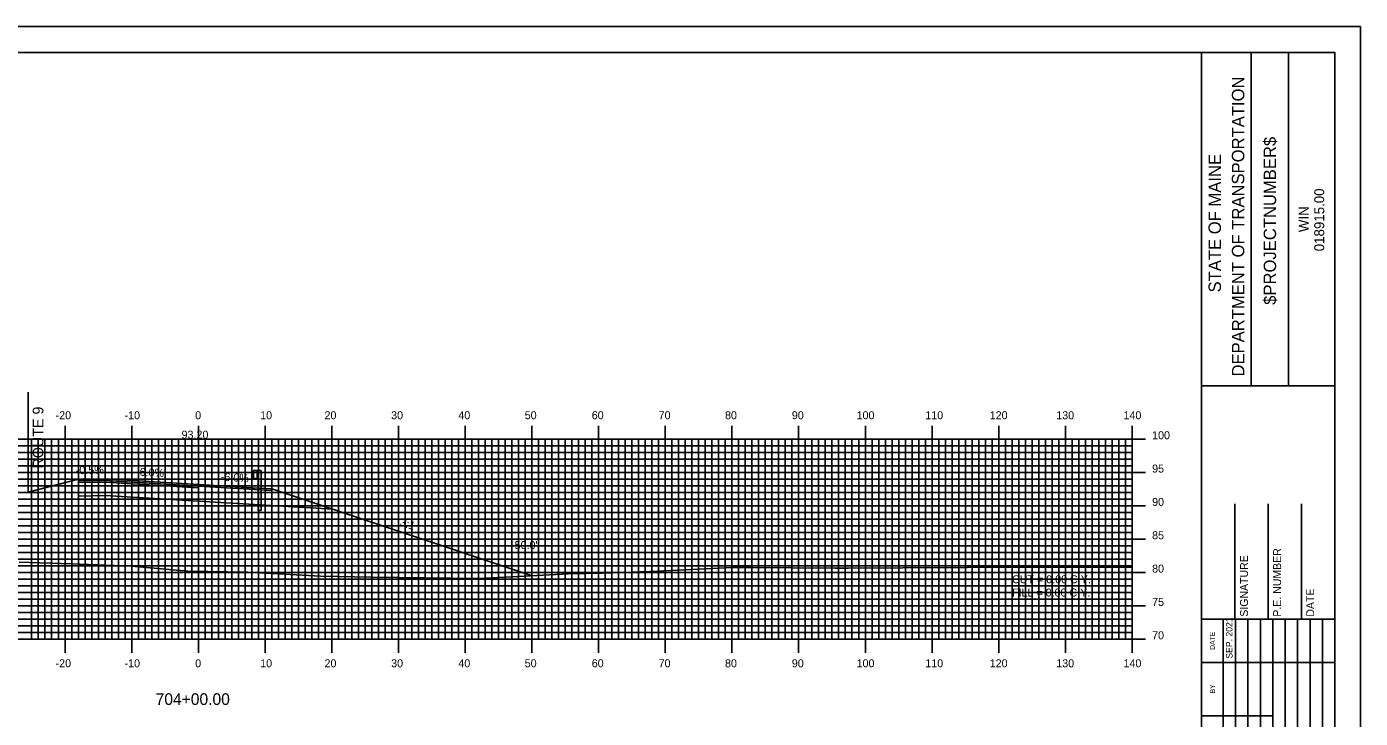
# Model space of a CAD drawing. Extents: x 853329 to 853673, y 364366 to 364586.
# Drawn here: x 853469.5 to 853669.4, y 364481.9 to 364585.7 of the extents above; entities that cross this region are included whole.
import ezdxf

# ---------------------------------------------------------------- set-up
doc = ezdxf.new("R2010")
doc.units = 0
for name, color, linetype in [('ANNOTATION', 7, 'Continuous'), ('BORDER', 7, 'Continuous'), ('D_Guardrail_Beam_Rt', 7, 'Continuous'), ('D_Roadway_Centerline_Text', 7, 'Continuous'), ('D_Roadway_Edge_Shoulder', 7, 'Continuous'), ('D_Roadway_Edge_TW', 7, 'Continuous'), ('D_Roadway_Pavement', 7, 'Continuous'), ('D_Roadway_SlopeLines', 7, 'Continuous'), ('D_Roadway_SubGrade', 7, 'Continuous'), ('D_Text_Standard', 7, 'Continuous'), ('H_V ANNOTATION', 7, 'Continuous'), ('MAJOR', 7, 'Continuous'), ('MINOR', 7, 'Continuous'), ('PLOT BOUNDARY', 7, 'Continuous'), ('S_Roadway_Centerline', 7, 'Continuous')]:
    doc.layers.add(name, color=color, linetype=linetype)

msp = doc.modelspace()

# ---------------------------------------------------------------- linework, layer by layer
at = {"layer": 'BORDER'}
for p, q in [((853645.6, 364371.79), (853645.6, 364581.79)), ((853653.06, 364531.78), (853653.06, 364581.78)), ((853658.65, 364531.78), (853658.65, 364581.78)), ((853645.61, 364531.78), (853665.6, 364531.78)), ((853650.6, 364496.79), (853650.6, 364514.09)), ((853655.6, 364496.79), (853655.6, 364514.09)), ((853660.6, 364496.79), (853660.6, 364514.09)), ((853645.6, 364496.79), (853665.6, 364496.79))]:
    msp.add_line(p, q, dxfattribs=at)
msp.add_lwpolyline([(853345.6, 364371.79), (853665.6, 364371.79), (853665.6, 364581.79), (853345.6, 364581.79)], close=True, dxfattribs=at)
for points in [[(853648.83, 364490.29), (853648.83, 364496.79)], [(853650.7, 364461.8), (853650.7, 364496.79)], [(853652.56, 364496.79), (853652.56, 364461.8)], [(853654.43, 364461.8), (853654.43, 364496.79)], [(853656.29, 364461.8), (853656.29, 364496.79)], [(853658.15, 364461.8), (853658.15, 364496.79)], [(853660.02, 364461.8), (853660.02, 364496.79)], [(853661.88, 364461.8), (853661.88, 364496.79)], [(853663.74, 364461.8), (853663.74, 364496.79)], [(853648.84, 364461.8), (853648.84, 364495.38)], [(853645.6, 364490.29), (853665.6, 364490.29)], [(853645.6, 364482.29), (853648.84, 364482.29)], [(853648.83, 364482.29), (853656.29, 364482.29)]]:
    msp.add_lwpolyline(points, dxfattribs=at)
at = {"layer": 'D_Guardrail_Beam_Rt'}
for p, q in [((853503.39, 364518.99), (853503.24, 364518.89)), ((853503.24, 364518.74), (853503.44, 364518.61)), ((853503.48, 364519.01), (853503.4, 364518.99)), ((853503.48, 364519.09), (853504.16, 364519.09)), ((853503.48, 364517.92), (853503.48, 364519.09)), ((853504, 364519.09), (853504, 364517.92)), ((853504.1, 364519.09), (853504.1, 364517.92)), ((853504.16, 364519.09), (853504.63, 364519.09)), ((853504.16, 364519.09), (853504.16, 364517.92)), ((853504.63, 364519.09), (853504.63, 364513.09)), ((853503.44, 364518.41), (853503.24, 364518.27)), ((853503.24, 364518.13), (853503.39, 364518.03)), ((853503.4, 364518.02), (853503.48, 364518.01)), ((853503.47, 364518.54), (853503.47, 364518.47)), ((853504.16, 364517.92), (853503.48, 364517.92)), ((853504.14, 364513.09), (853504.14, 364517.92)), ((853504.14, 364513.09), (853504.63, 364513.09))]:
    msp.add_line(p, q, dxfattribs=at)
for centre, major_axis, start_param, end_param in [((853503.29, 364518.81), (-0.0877, 0), 5.323254, 7.243116), ((853503.41, 364518.95), (-0.0417, 0), 4.907132, 5.323254), ((853503.29, 364518.2), (-0.0877, 0), 5.323254, 7.243116), ((853503.41, 364518.06), (-0.0417, 0), 0.959931, 1.376053), ((853503.39, 364518.54), (0.0789, 0), 0, 0.959931), ((853503.39, 364518.47), (0.0789, 0), 5.323254, 6.283185)]:
    msp.add_ellipse(centre, major_axis=major_axis, ratio=0.995501, start_param=start_param, end_param=end_param, dxfattribs=at)
at = {"layer": 'D_Roadway_Edge_Shoulder'}
for p, q in [((853477.2, 364517.37), (853477.2, 364517.81)), ((853481.2, 364517.58), (853477.2, 364517.56)), ((853481.2, 364517.33), (853477.2, 364517.31))]:
    msp.add_line(p, q, dxfattribs=at)
for points in [[(853481.2, 364517.83), (853477.2, 364517.81), (853469.7, 364515.87)], [(853481.2, 364515.33), (853477.2, 364515.25), (853477.2, 364517.37)]]:
    msp.add_lwpolyline(points, dxfattribs=at)
msp.add_lwpolyline([(853495.2, 364516.99), (853503.2, 364516.51), (853503.2, 364516.51), (853506.2, 364516.33), (853506.2, 364516.08), (853495.2, 364516.74)], close=True, dxfattribs=at)
at = {"layer": 'D_Roadway_Edge_TW'}
msp.add_lwpolyline([(853481.2, 364517.83), (853495.2, 364516.99), (853495.2, 364516.74), (853481.2, 364517.58)], close=True, dxfattribs=at)
at = {"layer": 'D_Roadway_Pavement'}
msp.add_lwpolyline([(853481.2, 364517.58), (853495.2, 364516.74), (853495.2, 364516.49), (853481.2, 364517.33)], close=True, dxfattribs=at)
msp.add_lwpolyline([(853495.2, 364516.74), (853495.2, 364516.49)], dxfattribs=at)
msp.add_lwpolyline([(853495.2, 364516.74), (853495.2, 364516.49)], dxfattribs=at)
msp.add_lwpolyline([(853495.2, 364516.74), (853495.2, 364516.49)], dxfattribs=at)
at = {"layer": 'D_Roadway_SlopeLines'}
msp.add_lwpolyline([(853506.2, 364516.33), (853545.23, 364503.32)], dxfattribs=at)
at = {"layer": 'D_Roadway_SubGrade'}
msp.add_line((853469.7, 364530.83), (853469.7, 364515.87), dxfattribs=at)
for points in [[(853481.2, 364517.33), (853495.2, 364516.49), (853495.2, 364514.49), (853481.2, 364515.33)], [(853495.2, 364516.49), (853495.2, 364516.74), (853506.2, 364516.08), (853506.2, 364516.33), (853515.35, 364513.28), (853495.2, 364514.49)]]:
    msp.add_lwpolyline(points, close=True, dxfattribs=at)
at = {"layer": 'MAJOR'}
for p, q in [((853475.2, 364525.79), (853475.2, 364523.79)), ((853485.2, 364525.79), (853485.2, 364523.79)), ((853495.2, 364525.79), (853495.2, 364523.79)), ((853505.2, 364525.79), (853505.2, 364523.79)), ((853515.2, 364525.79), (853515.2, 364523.79)), ((853525.2, 364525.79), (853525.2, 364523.79)), ((853535.2, 364525.79), (853535.2, 364523.79)), ((853545.2, 364525.79), (853545.2, 364523.79)), ((853555.2, 364525.79), (853555.2, 364523.79)), ((853565.2, 364525.79), (853565.2, 364523.79)), ((853575.2, 364525.79), (853575.2, 364523.79)), ((853585.2, 364525.79), (853585.2, 364523.79)), ((853595.2, 364525.79), (853595.2, 364523.79)), ((853605.2, 364525.79), (853605.2, 364523.79)), ((853615.2, 364525.79), (853615.2, 364523.79)), ((853625.2, 364525.79), (853625.2, 364523.79)), ((853635.2, 364525.79), (853635.2, 364523.79)), ((853355.2, 364523.79), (853635.2, 364523.79)), ((853355.2, 364523.79), (853635.2, 364523.79)), ((853475.2, 364493.79), (853475.2, 364523.79)), ((853485.2, 364493.79), (853485.2, 364523.79)), ((853495.2, 364493.79), (853495.2, 364523.79)), ((853505.2, 364493.79), (853505.2, 364523.79)), ((853515.2, 364493.79), (853515.2, 364523.79)), ((853525.2, 364493.79), (853525.2, 364523.79)), ((853535.2, 364493.79), (853535.2, 364523.79)), ((853545.2, 364493.79), (853545.2, 364523.79)), ((853555.2, 364493.79), (853555.2, 364523.79)), ((853565.2, 364493.79), (853565.2, 364523.79)), ((853575.2, 364493.79), (853575.2, 364523.79)), ((853585.2, 364493.79), (853585.2, 364523.79)), ((853595.2, 364493.79), (853595.2, 364523.79)), ((853605.2, 364493.79), (853605.2, 364523.79)), ((853615.2, 364493.79), (853615.2, 364523.79)), ((853625.2, 364493.79), (853625.2, 364523.79)), ((853637.21, 364523.79), (853633.2, 364523.79)), ((853635.2, 364493.79), (853635.2, 364523.79)), ((853635.2, 364493.79), (853635.2, 364523.79)), ((853355.2, 364518.79), (853635.2, 364518.79)), ((853637.21, 364518.79), (853633.2, 364518.79)), ((853355.2, 364513.79), (853635.2, 364513.79)), ((853637.21, 364513.79), (853633.2, 364513.79)), ((853355.2, 364508.79), (853635.2, 364508.79)), ((853637.21, 364508.79), (853633.2, 364508.79)), ((853355.2, 364503.79), (853635.2, 364503.79)), ((853637.21, 364503.79), (853633.2, 364503.79)), ((853355.2, 364498.79), (853635.2, 364498.79)), ((853637.21, 364498.79), (853633.2, 364498.79)), ((853355.2, 364493.79), (853635.2, 364493.79)), ((853355.2, 364493.79), (853635.2, 364493.79)), ((853475.2, 364491.78), (853475.2, 364493.79)), ((853485.2, 364491.78), (853485.2, 364493.79)), ((853495.2, 364491.78), (853495.2, 364493.79)), ((853505.2, 364491.78), (853505.2, 364493.79)), ((853515.2, 364491.78), (853515.2, 364493.79)), ((853525.2, 364491.78), (853525.2, 364493.79)), ((853535.2, 364491.78), (853535.2, 364493.79)), ((853545.2, 364491.78), (853545.2, 364493.79)), ((853555.2, 364491.78), (853555.2, 364493.79)), ((853565.2, 364491.78), (853565.2, 364493.79)), ((853575.2, 364491.78), (853575.2, 364493.79)), ((853585.2, 364491.78), (853585.2, 364493.79)), ((853595.2, 364491.78), (853595.2, 364493.79)), ((853605.2, 364491.78), (853605.2, 364493.79)), ((853615.2, 364491.78), (853615.2, 364493.79)), ((853625.2, 364491.78), (853625.2, 364493.79)), ((853637.21, 364493.79), (853633.2, 364493.79)), ((853635.2, 364491.78), (853635.2, 364493.79))]:
    msp.add_line(p, q, dxfattribs=at)
at = {"layer": 'MINOR'}
for p, q in [((853355.2, 364522.79), (853635.2, 364522.79)), ((853470.2, 364493.79), (853470.2, 364523.79)), ((853471.2, 364493.79), (853471.2, 364523.79)), ((853472.2, 364493.79), (853472.2, 364523.79)), ((853473.2, 364493.79), (853473.2, 364523.79)), ((853474.2, 364493.79), (853474.2, 364523.79)), ((853476.2, 364493.79), (853476.2, 364523.79)), ((853477.2, 364493.79), (853477.2, 364523.79)), ((853478.2, 364493.79), (853478.2, 364523.79)), ((853479.2, 364493.79), (853479.2, 364523.79)), ((853480.2, 364493.79), (853480.2, 364523.79)), ((853481.2, 364493.79), (853481.2, 364523.79)), ((853482.2, 364493.79), (853482.2, 364523.79)), ((853483.2, 364493.79), (853483.2, 364523.79)), ((853484.2, 364493.79), (853484.2, 364523.79)), ((853486.2, 364493.79), (853486.2, 364523.79)), ((853487.2, 364493.79), (853487.2, 364523.79)), ((853488.2, 364493.79), (853488.2, 364523.79)), ((853489.2, 364493.79), (853489.2, 364523.79)), ((853490.2, 364493.79), (853490.2, 364523.79)), ((853491.2, 364493.79), (853491.2, 364523.79)), ((853492.2, 364493.79), (853492.2, 364523.79)), ((853493.2, 364493.79), (853493.2, 364523.79)), ((853494.2, 364493.79), (853494.2, 364523.79)), ((853496.2, 364493.79), (853496.2, 364523.79)), ((853497.2, 364493.79), (853497.2, 364523.79)), ((853498.2, 364493.79), (853498.2, 364523.79)), ((853499.2, 364493.79), (853499.2, 364523.79)), ((853500.2, 364493.79), (853500.2, 364523.79)), ((853501.2, 364493.79), (853501.2, 364523.79)), ((853502.2, 364493.79), (853502.2, 364523.79)), ((853503.2, 364493.79), (853503.2, 364523.79)), ((853504.2, 364493.79), (853504.2, 364523.79)), ((853506.2, 364493.79), (853506.2, 364523.79)), ((853507.2, 364493.79), (853507.2, 364523.79)), ((853508.2, 364493.79), (853508.2, 364523.79)), ((853509.2, 364493.79), (853509.2, 364523.79)), ((853510.2, 364493.79), (853510.2, 364523.79)), ((853511.2, 364493.79), (853511.2, 364523.79)), ((853512.2, 364493.79), (853512.2, 364523.79)), ((853513.2, 364493.79), (853513.2, 364523.79)), ((853514.2, 364493.79), (853514.2, 364523.79)), ((853516.2, 364493.79), (853516.2, 364523.79)), ((853517.2, 364493.79), (853517.2, 364523.79)), ((853518.2, 364493.79), (853518.2, 364523.79)), ((853519.2, 364493.79), (853519.2, 364523.79)), ((853520.2, 364493.79), (853520.2, 364523.79)), ((853521.2, 364493.79), (853521.2, 364523.79)), ((853522.2, 364493.79), (853522.2, 364523.79)), ((853523.2, 364493.79), (853523.2, 364523.79)), ((853524.2, 364493.79), (853524.2, 364523.79)), ((853526.2, 364493.79), (853526.2, 364523.79)), ((853527.2, 364493.79), (853527.2, 364523.79)), ((853528.2, 364493.79), (853528.2, 364523.79)), ((853529.2, 364493.79), (853529.2, 364523.79)), ((853530.2, 364493.79), (853530.2, 364523.79)), ((853531.2, 364493.79), (853531.2, 364523.79)), ((853532.2, 364493.79), (853532.2, 364523.79)), ((853533.2, 364493.79), (853533.2, 364523.79)), ((853534.2, 364493.79), (853534.2, 364523.79)), ((853536.2, 364493.79), (853536.2, 364523.79)), ((853537.2, 364493.79), (853537.2, 364523.79)), ((853538.2, 364493.79), (853538.2, 364523.79)), ((853539.2, 364493.79), (853539.2, 364523.79)), ((853540.2, 364493.79), (853540.2, 364523.79)), ((853541.2, 364493.79), (853541.2, 364523.79)), ((853542.2, 364493.79), (853542.2, 364523.79)), ((853543.2, 364493.79), (853543.2, 364523.79)), ((853544.2, 364493.79), (853544.2, 364523.79)), ((853546.2, 364493.79), (853546.2, 364523.79)), ((853547.2, 364493.79), (853547.2, 364523.79)), ((853548.2, 364493.79), (853548.2, 364523.79)), ((853549.2, 364493.79), (853549.2, 364523.79)), ((853550.2, 364493.79), (853550.2, 364523.79)), ((853551.2, 364493.79), (853551.2, 364523.79)), ((853552.2, 364493.79), (853552.2, 364523.79)), ((853553.2, 364493.79), (853553.2, 364523.79)), ((853554.2, 364493.79), (853554.2, 364523.79)), ((853556.2, 364493.79), (853556.2, 364523.79)), ((853557.2, 364493.79), (853557.2, 364523.79)), ((853558.2, 364493.79), (853558.2, 364523.79)), ((853559.2, 364493.79), (853559.2, 364523.79)), ((853560.2, 364493.79), (853560.2, 364523.79)), ((853561.2, 364493.79), (853561.2, 364523.79)), ((853562.2, 364493.79), (853562.2, 364523.79)), ((853563.2, 364493.79), (853563.2, 364523.79)), ((853564.2, 364493.79), (853564.2, 364523.79)), ((853566.2, 364493.79), (853566.2, 364523.79)), ((853567.2, 364493.79), (853567.2, 364523.79)), ((853568.2, 364493.79), (853568.2, 364523.79)), ((853569.2, 364493.79), (853569.2, 364523.79)), ((853570.2, 364493.79), (853570.2, 364523.79)), ((853571.2, 364493.79), (853571.2, 364523.79)), ((853572.2, 364493.79), (853572.2, 364523.79)), ((853573.2, 364493.79), (853573.2, 364523.79)), ((853574.2, 364493.79), (853574.2, 364523.79)), ((853576.2, 364493.79), (853576.2, 364523.79)), ((853577.2, 364493.79), (853577.2, 364523.79)), ((853578.2, 364493.79), (853578.2, 364523.79)), ((853579.2, 364493.79), (853579.2, 364523.79)), ((853580.2, 364493.79), (853580.2, 364523.79)), ((853581.2, 364493.79), (853581.2, 364523.79)), ((853582.2, 364493.79), (853582.2, 364523.79)), ((853583.2, 364493.79), (853583.2, 364523.79)), ((853584.2, 364493.79), (853584.2, 364523.79)), ((853586.2, 364493.79), (853586.2, 364523.79)), ((853587.2, 364493.79), (853587.2, 364523.79)), ((853588.2, 364493.79), (853588.2, 364523.79)), ((853589.2, 364493.79), (853589.2, 364523.79)), ((853590.2, 364493.79), (853590.2, 364523.79)), ((853591.2, 364493.79), (853591.2, 364523.79)), ((853592.2, 364493.79), (853592.2, 364523.79)), ((853593.2, 364493.79), (853593.2, 364523.79)), ((853594.2, 364493.79), (853594.2, 364523.79)), ((853596.2, 364493.79), (853596.2, 364523.79)), ((853597.2, 364493.79), (853597.2, 364523.79)), ((853598.2, 364493.79), (853598.2, 364523.79)), ((853599.2, 364493.79), (853599.2, 364523.79)), ((853600.2, 364493.79), (853600.2, 364523.79)), ((853601.2, 364493.79), (853601.2, 364523.79)), ((853602.2, 364493.79), (853602.2, 364523.79)), ((853603.2, 364493.79), (853603.2, 364523.79)), ((853604.2, 364493.79), (853604.2, 364523.79)), ((853606.2, 364493.79), (853606.2, 364523.79)), ((853607.2, 364493.79), (853607.2, 364523.79)), ((853608.2, 364493.79), (853608.2, 364523.79)), ((853609.2, 364493.79), (853609.2, 364523.79)), ((853610.2, 364493.79), (853610.2, 364523.79)), ((853611.2, 364493.79), (853611.2, 364523.79)), ((853612.2, 364493.79), (853612.2, 364523.79)), ((853613.2, 364493.79), (853613.2, 364523.79)), ((853614.2, 364493.79), (853614.2, 364523.79)), ((853616.2, 364493.79), (853616.2, 364523.79)), ((853617.2, 364493.79), (853617.2, 364523.79)), ((853618.2, 364493.79), (853618.2, 364523.79)), ((853619.2, 364493.79), (853619.2, 364523.79)), ((853620.2, 364493.79), (853620.2, 364523.79)), ((853621.2, 364493.79), (853621.2, 364523.79)), ((853622.2, 364493.79), (853622.2, 364523.79)), ((853623.2, 364493.79), (853623.2, 364523.79)), ((853624.2, 364493.79), (853624.2, 364523.79)), ((853626.2, 364493.79), (853626.2, 364523.79)), ((853627.2, 364493.79), (853627.2, 364523.79)), ((853628.2, 364493.79), (853628.2, 364523.79)), ((853629.2, 364493.79), (853629.2, 364523.79)), ((853630.2, 364493.79), (853630.2, 364523.79)), ((853631.2, 364493.79), (853631.2, 364523.79)), ((853632.2, 364493.79), (853632.2, 364523.79)), ((853633.2, 364493.79), (853633.2, 364523.79)), ((853635.2, 364522.79), (853633.2, 364522.79)), ((853634.2, 364493.79), (853634.2, 364523.79)), ((853355.2, 364521.79), (853635.2, 364521.79)), ((853355.2, 364520.79), (853635.2, 364520.79)), ((853635.2, 364521.79), (853633.2, 364521.79)), ((853635.2, 364520.79), (853633.2, 364520.79)), ((853355.2, 364519.79), (853635.2, 364519.79)), ((853635.2, 364519.79), (853633.2, 364519.79)), ((853355.2, 364517.79), (853635.2, 364517.79)), ((853355.2, 364516.79), (853635.2, 364516.79)), ((853635.2, 364517.79), (853633.2, 364517.79)), ((853635.2, 364516.79), (853633.2, 364516.79)), ((853355.2, 364515.79), (853635.2, 364515.79)), ((853355.2, 364514.79), (853635.2, 364514.79)), ((853635.2, 364515.79), (853633.2, 364515.79)), ((853635.2, 364514.79), (853633.2, 364514.79)), ((853355.2, 364512.79), (853635.2, 364512.79)), ((853635.2, 364512.79), (853633.2, 364512.79)), ((853355.2, 364511.79), (853635.2, 364511.79)), ((853355.2, 364510.79), (853635.2, 364510.79)), ((853635.2, 364511.79), (853633.2, 364511.79)), ((853635.2, 364510.79), (853633.2, 364510.79)), ((853355.2, 364509.79), (853635.2, 364509.79)), ((853635.2, 364509.79), (853633.2, 364509.79)), ((853355.2, 364507.79), (853635.2, 364507.79)), ((853355.2, 364506.79), (853635.2, 364506.79)), ((853635.2, 364507.79), (853633.2, 364507.79)), ((853635.2, 364506.79), (853633.2, 364506.79)), ((853355.2, 364505.79), (853635.2, 364505.79)), ((853355.2, 364504.79), (853635.2, 364504.79)), ((853635.2, 364505.79), (853633.2, 364505.79)), ((853635.2, 364504.79), (853633.2, 364504.79)), ((853355.2, 364502.79), (853635.2, 364502.79)), ((853635.2, 364502.79), (853633.2, 364502.79)), ((853355.2, 364501.79), (853635.2, 364501.79)), ((853355.2, 364500.79), (853635.2, 364500.79)), ((853635.2, 364501.79), (853633.2, 364501.79)), ((853635.2, 364500.79), (853633.2, 364500.79)), ((853355.2, 364499.79), (853635.2, 364499.79)), ((853635.2, 364499.79), (853633.2, 364499.79)), ((853355.2, 364497.79), (853635.2, 364497.79)), ((853355.2, 364496.79), (853635.2, 364496.79)), ((853635.2, 364497.79), (853633.2, 364497.79)), ((853635.2, 364496.79), (853633.2, 364496.79)), ((853355.2, 364495.79), (853635.2, 364495.79)), ((853355.2, 364494.79), (853635.2, 364494.79)), ((853635.2, 364495.79), (853633.2, 364495.79)), ((853635.2, 364494.79), (853633.2, 364494.79))]:
    msp.add_line(p, q, dxfattribs=at)
at = {"layer": 'PLOT BOUNDARY'}
msp.add_lwpolyline([(853329.42, 364365.67), (853669.42, 364365.67), (853669.42, 364585.67), (853329.42, 364585.67)], close=True, dxfattribs=at)
at = {"layer": 'S_Roadway_Centerline'}
msp.add_lwpolyline([(853468.35, 364505.35), (853476.14, 364505.13), (853485.19, 364504.78), (853493.64, 364504.02), (853502.62, 364503.87), (853513.52, 364503.27), (853521.17, 364503.1), (853537.03, 364502.91), (853537.27, 364502.9), (853537.36, 364502.89), (853550.67, 364503.61), (853555.81, 364503.73), (853562.93, 364503.98), (853575.27, 364504.57), (853575.9, 364504.56), (853577.95, 364504.55), (853590.7, 364504.46), (853592.61, 364504.46), (853600.81, 364504.5), (853610.45, 364504.56), (853622.27, 364504.61), (853626.43, 364504.6), (853628.46, 364504.63), (853635.2, 364504.57)], dxfattribs=at)

# ---------------------------------------------------------------- texts
at = {"layer": 'ANNOTATION'}
for s, height, rotation, p in [('ROUTE 9', 1.6, 90, (853471.96, 364519.41)), ('-0.5%', 1.2, 1.1458, (853476.83, 364518.54)), ('6.0%', 1.2, 356.5664, (853486.36, 364518.32)), ('-6.0%', 1.2, 356.5664, (853498.54, 364517.59)), ('3:1', 1.2, 341.5651, (853525.32, 364510.86))]:
    msp.add_text(s, height=height, rotation=rotation, dxfattribs=at).set_placement(p)
at = {"layer": 'BORDER'}
for s, height, p in [('DEPARTMENT OF TRANSPORTATION', 1.8635, (853652.02, 364533.2)), ('$PROJECTNUMBER$', 1.8635, (853656.79, 364543.95)), ('STATE OF MAINE', 1.8635, (853648.52, 364545.81)), ('018915.00', 1.491, (853664, 364551.98)), ('WIN', 1.491, (853661.68, 364554.85)), ('P.E. NUMBER', 1.1811, (853657.53, 364497.18)), ('SIGNATURE', 1.181, (853652.57, 364497.18)), ('DATE', 1.181, (853662.49, 364497.18)), ('SEP. 2021', 0.969, (853650.25, 364490.88)), ('DATE', 0.743, (853647.61, 364492.2)), ('BY', 0.743, (853647.61, 364485.66))]:
    msp.add_text(s, height=height, rotation=90, dxfattribs=at).set_placement(p)
at = {"layer": 'D_Roadway_Centerline_Text'}
msp.add_text('93.20', height=1.2, dxfattribs=at).set_placement((853492.68, 364523.88))
at = {"layer": 'D_Text_Standard'}
for s, p in [("50.0'", (853542.62, 364507.32)), ('CUT = 0.00 C.Y.', (853617.2, 364502.19)), ('FILL = 0.00 C.Y.', (853617.2, 364500.2))]:
    msp.add_text(s, height=1.2, dxfattribs=at).set_placement(p)
at = {"layer": 'H_V ANNOTATION'}
for s, height, p in [('-20', 1.2, (853473.79, 364526.79)), ('-10', 1.2, (853484.13, 364526.79)), ('0', 1.2, (853494.72, 364526.79)), ('10', 1.2, (853504.46, 364526.79)), ('20', 1.2, (853514.11, 364526.79)), ('30', 1.2, (853524.1, 364526.79)), ('40', 1.2, (853534.18, 364526.79)), ('50', 1.2, (853544.13, 364526.79)), ('60', 1.2, (853554.18, 364526.79)), ('70', 1.2, (853564.21, 364526.79)), ('80', 1.2, (853574.16, 364526.79)), ('90', 1.2, (853584.18, 364526.79)), ('100', 1.2, (853593.89, 364526.79)), ('110', 1.2, (853604.19, 364526.79)), ('120', 1.2, (853613.85, 364526.79)), ('130', 1.2, (853623.83, 364526.79)), ('140', 1.2, (853633.91, 364526.79)), ('100', 1.2, (853638.2, 364523.79)), ('95', 1.2, (853638.2, 364518.79)), ('90', 1.2, (853638.2, 364513.79)), ('85', 1.2, (853638.2, 364508.79)), ('80', 1.2, (853638.2, 364503.79)), ('75', 1.2, (853638.2, 364498.79)), ('70', 1.2, (853638.2, 364493.79)), ('-20', 1.2, (853473.79, 364489.59)), ('-10', 1.2, (853484.13, 364489.59)), ('0', 1.2, (853494.72, 364489.59)), ('10', 1.2, (853504.46, 364489.59)), ('20', 1.2, (853514.11, 364489.59)), ('30', 1.2, (853524.1, 364489.59)), ('40', 1.2, (853534.18, 364489.59)), ('50', 1.2, (853544.13, 364489.59)), ('60', 1.2, (853554.18, 364489.59)), ('70', 1.2, (853564.21, 364489.59)), ('80', 1.2, (853574.16, 364489.59)), ('90', 1.2, (853584.18, 364489.59)), ('100', 1.2, (853593.89, 364489.59)), ('110', 1.2, (853604.19, 364489.59)), ('120', 1.2, (853613.85, 364489.59)), ('130', 1.2, (853623.83, 364489.59)), ('140', 1.2, (853633.91, 364489.59)), ('704+00.00', 1.75, (853488.79, 364483.94))]:
    msp.add_text(s, height=height, dxfattribs=at).set_placement(p)

doc.saveas('drawing.dxf')
